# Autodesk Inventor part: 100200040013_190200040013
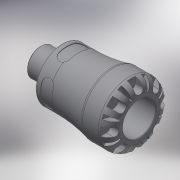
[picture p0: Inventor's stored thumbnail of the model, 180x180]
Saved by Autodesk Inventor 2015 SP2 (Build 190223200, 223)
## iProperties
Created: 2016-12
Part Number: 100200040013_190200040013
Material: Generic
Description: PLASSON MALE ADAPTOR 40X1.1/4" SERIES 1
Document SubType Name: Modeling
Designer: KIM
Mass: 447.839 g
Surface Area: 722.341 cm^2
Volume: 447.839 cm^3
Density: 1 g/cm^3
Appearance: Default
Author: KIM
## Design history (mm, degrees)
derived "1002.ipt"
feature "Solid1::1002.ipt"
tag "TaggingFeature1"
body "Solid1"
other parameters: "d0" = 106, "d1" = 30.66, "d6" = 73, "d8" = 59.5, "d13" = 8, "d14" = 8, "d15" = 0, "d17" = 360 deg, "d19" = 8 deg, "d20" = 0.8, "d21" = 0.8, "d22" = 8 deg, "d24" = 0, "d26" = 360 deg, "d32" = 0.925, "d33" = 7, "d34" = 41.91, "d35" = 5, "d38" = 21, "d39" = 1.2573, "d42" = 14, "d43" = 9.2, "d45" = 15.68, "d46" = 0, "d59" = 360 deg, "d61" = 11.9, "d62" = 0.8, "d64" = 0, "d65" = 0.7, "H_" = 106, "l_" = 73, "R_" = 41.91, "l_2" = 21, "d9" = 10
